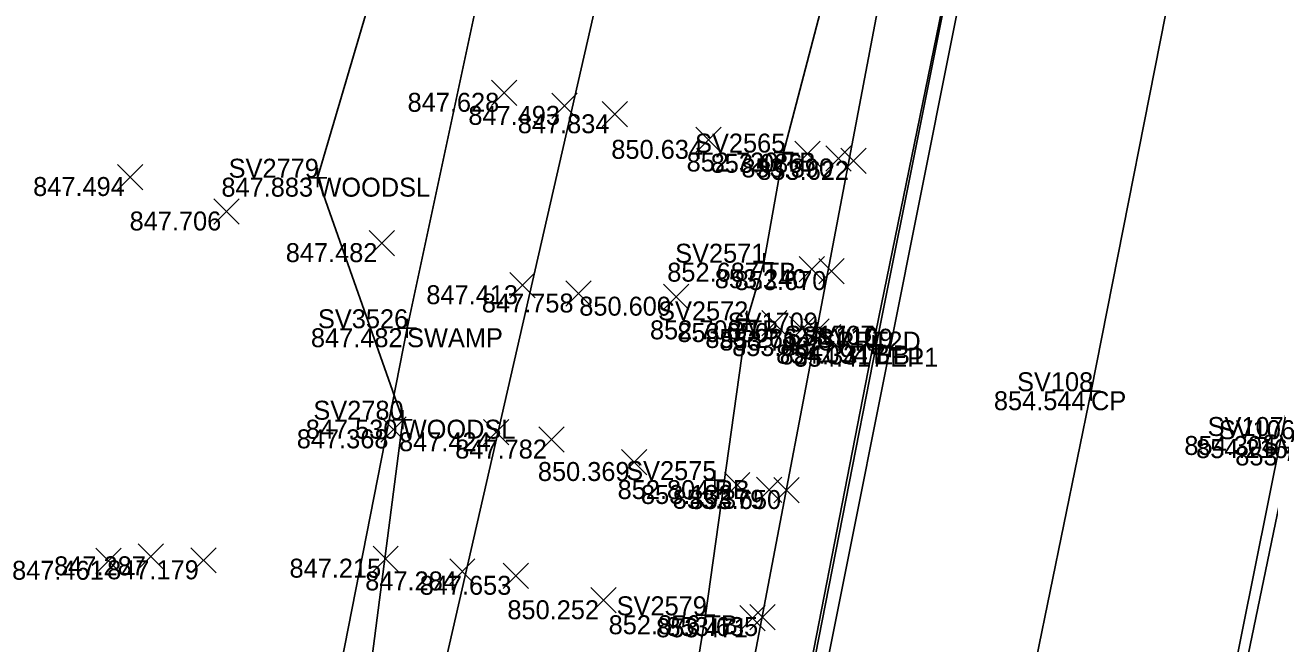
# Model space of a CAD drawing. Extents: x 2228183 to 2230895, y 679226 to 682223.
# Drawn here: x 2228275.5 to 2228341.1, y 680675.1 to 680707.7 of the extents above; entities that cross this region are included whole.
import ezdxf

# ---------------------------------------------------------------- set-up
doc = ezdxf.new("R2010")
doc.units = 0
for name, color, linetype in [('HY_X_Water_Edge', 7, 'Continuous'), ('PV_X_COP', 7, 'Continuous'), ('PV_X_EOP', 7, 'Continuous'), ('PV_X_Shoulder_Aggregate', 7, 'Continuous'), ('RD_X_GR_Rt', 7, 'Continuous'), ('SC_Scratch1', 7, 'Continuous'), ('SV_P_Control_Cells_Set', 7, 'Continuous'), ('SV_X_Break_Lines', 7, 'Continuous'), ('SV_X_Random_Point', 7, 'Continuous'), ('SV_X_Shot_Marker', 7, 'Continuous'), ('SV_X_Text_Comment', 7, 'Continuous'), ('SV_X_Top_of_Bank', 7, 'Continuous'), ('UT_X_Water', 7, 'Continuous'), ('VG_X_Tree_Line_Rt', 7, 'Continuous')]:
    doc.layers.add(name, color=color, linetype=linetype)

msp = doc.modelspace()

# ---------------------------------------------------------------- linework, layer by layer
at = {"layer": 'HY_X_Water_Edge'}
msp.add_lwpolyline([(2228257.254, 680599.372), (2228272.802, 680617.571), (2228282.168, 680631.469), (2228288.524, 680655.152), (2228295.689, 680691.668), (2228303.446, 680727.882), (2228301.785, 680777.477), (2228295.766, 680798.984)], dxfattribs=at)
at = {"layer": 'PV_X_COP'}
msp.add_lwpolyline([(2228326.722, 680663.726), (2228331.754, 680688.345), (2228336.524, 680712.498), (2228341.43, 680737.322), (2228346.158, 680761.464), (2228351.192, 680786.345), (2228355.877, 680809.999), (2228360.846, 680834.68), (2228365.727, 680859.369), (2228370.534, 680883.512), (2228375.578, 680908.155), (2228380.641, 680932.739), (2228385.533, 680957.104), (2228390.417, 680981.565)], dxfattribs=at)
at = {"layer": 'PV_X_EOP'}
for points in [[(2228316.271, 680666.166), (2228321.17, 680690.642), (2228325.981, 680714.788), (2228330.885, 680739.479), (2228335.691, 680763.827), (2228340.555, 680788.666), (2228345.277, 680812.618), (2228350.247, 680837.119), (2228355.301, 680861.724), (2228360.108, 680885.906), (2228365.09, 680910.821), (2228370.043, 680935.115), (2228374.935, 680959.317), (2228379.826, 680983.84)], [(2228336.903, 680661.667), (2228341.796, 680685.984), (2228346.631, 680710.376), (2228351.501, 680734.874), (2228356.245, 680759.284), (2228361.077, 680783.608), (2228365.966, 680808.133), (2228370.927, 680832.455), (2228375.827, 680856.961), (2228380.73, 680881.352), (2228385.664, 680905.987), (2228390.725, 680930.452), (2228395.696, 680954.82), (2228400.463, 680979.305)]]:
    msp.add_lwpolyline(points, dxfattribs=at)
at = {"layer": 'PV_X_Shoulder_Aggregate'}
for points in [[(2228315.628, 680666.277), (2228320.418, 680690.758), (2228325.257, 680714.912), (2228330.316, 680739.567), (2228335.324, 680763.916), (2228340.217, 680788.76), (2228345.101, 680812.661), (2228350.01, 680837.187), (2228354.942, 680861.825), (2228359.826, 680886.012), (2228364.882, 680910.859), (2228369.759, 680935.173), (2228374.64, 680959.326), (2228379.525, 680983.909)], [(2228337.368, 680661.526), (2228342.398, 680685.817), (2228347.341, 680710.233), (2228352.226, 680734.701), (2228356.994, 680759.156), (2228361.948, 680783.457), (2228366.728, 680807.919), (2228371.672, 680832.299), (2228376.565, 680856.801), (2228381.526, 680881.171), (2228386.516, 680905.781), (2228391.544, 680930.308), (2228396.514, 680954.638), (2228401.402, 680979.089)]]:
    msp.add_lwpolyline(points, dxfattribs=at)
at = {"layer": 'RD_X_GR_Rt'}
msp.add_lwpolyline([(2228336.966, 680805.161), (2228336.298, 680795.662), (2228335.499, 680789.809), (2228333.893, 680778.872), (2228331.445, 680764.638), (2228326.714, 680740.424), (2228321.884, 680715.76), (2228317.277, 680691.491), (2228312.595, 680666.948)], dxfattribs=at)
at = {"layer": 'SV_X_Break_Lines'}
msp.add_lwpolyline([(2228340.141, 680788.739), (2228338.031, 680778.231), (2228335.15, 680763.928), (2228332.621, 680751.514), (2228330.275, 680739.607), (2228325.198, 680714.925), (2228320.273, 680690.8), (2228315.504, 680666.348)], dxfattribs=at)
at = {"layer": 'SV_X_Random_Point'}
for p, q in [((2228300.146, 680703.419), (2228301.48, 680704.754)), ((2228300.146, 680704.754), (2228301.48, 680703.419)), ((2228303.316, 680702.73), (2228304.65, 680704.065)), ((2228303.316, 680704.065), (2228304.65, 680702.73)), ((2228305.979, 680702.287), (2228307.313, 680703.622)), ((2228305.979, 680703.622), (2228307.313, 680702.287)), ((2228310.912, 680700.937), (2228312.246, 680702.272)), ((2228310.912, 680702.272), (2228312.246, 680700.937)), ((2228316.133, 680700.201), (2228317.467, 680701.536)), ((2228316.133, 680701.536), (2228317.467, 680700.201)), ((2228317.763, 680699.957), (2228319.097, 680701.292)), ((2228317.763, 680701.292), (2228319.097, 680699.957)), ((2228318.563, 680699.828), (2228319.897, 680701.163)), ((2228318.563, 680701.163), (2228319.897, 680699.828)), ((2228280.424, 680698.977), (2228281.758, 680700.312)), ((2228280.424, 680700.312), (2228281.758, 680698.977)), ((2228285.493, 680697.158), (2228286.827, 680698.493)), ((2228285.493, 680698.493), (2228286.827, 680697.158)), ((2228293.696, 680695.489), (2228295.03, 680696.824)), ((2228293.696, 680696.824), (2228295.03, 680695.489)), ((2228316.358, 680694.111), (2228317.692, 680695.446)), ((2228316.358, 680695.446), (2228317.692, 680694.111)), ((2228317.409, 680694.016), (2228318.743, 680695.351)), ((2228317.409, 680695.351), (2228318.743, 680694.016)), ((2228301.1, 680693.27), (2228302.434, 680694.605)), ((2228301.1, 680694.605), (2228302.434, 680693.27)), ((2228304.063, 680692.832), (2228305.397, 680694.167)), ((2228304.063, 680694.167), (2228305.397, 680692.832)), ((2228309.215, 680692.665), (2228310.549, 680694)), ((2228309.215, 680694), (2228310.549, 680692.665)), ((2228314.387, 680691.273), (2228315.721, 680692.608)), ((2228314.387, 680692.608), (2228315.721, 680691.273)), ((2228315.851, 680690.961), (2228317.185, 680692.296)), ((2228315.851, 680692.296), (2228317.185, 680690.961)), ((2228316.61, 680690.824), (2228317.944, 680692.159)), ((2228316.61, 680692.159), (2228317.944, 680690.824)), ((2228317.233, 680690.533), (2228318.567, 680691.868)), ((2228317.233, 680691.868), (2228318.567, 680690.533)), ((2228294.305, 680685.667), (2228295.639, 680687.002)), ((2228294.305, 680687.002), (2228295.639, 680685.667)), ((2228299.717, 680685.515), (2228301.051, 680686.85)), ((2228299.717, 680686.85), (2228301.051, 680685.515)), ((2228302.633, 680685.128), (2228303.967, 680686.463)), ((2228302.633, 680686.463), (2228303.967, 680685.128)), ((2228307.002, 680683.944), (2228308.336, 680685.279)), ((2228307.002, 680685.279), (2228308.336, 680683.944)), ((2228312.428, 680682.731), (2228313.762, 680684.066)), ((2228312.428, 680684.066), (2228313.762, 680682.731)), ((2228314.109, 680682.481), (2228315.443, 680683.816)), ((2228314.109, 680683.816), (2228315.443, 680682.481)), ((2228315.024, 680682.465), (2228316.358, 680683.8)), ((2228315.024, 680683.8), (2228316.358, 680682.465)), ((2228279.274, 680678.732), (2228280.608, 680680.067)), ((2228279.274, 680680.067), (2228280.608, 680678.732)), ((2228281.505, 680678.968), (2228282.839, 680680.303)), ((2228281.505, 680680.303), (2228282.839, 680678.968)), ((2228284.287, 680678.758), (2228285.621, 680680.093)), ((2228284.287, 680680.093), (2228285.621, 680678.758)), ((2228293.891, 680678.845), (2228295.225, 680680.18)), ((2228293.891, 680680.18), (2228295.225, 680678.845)), ((2228297.934, 680678.173), (2228299.268, 680679.508)), ((2228297.934, 680679.508), (2228299.268, 680678.173)), ((2228300.748, 680677.942), (2228302.082, 680679.277)), ((2228300.748, 680679.277), (2228302.082, 680677.942)), ((2228305.382, 680676.651), (2228306.716, 680677.986)), ((2228305.382, 680677.986), (2228306.716, 680676.651)), ((2228313.234, 680675.699), (2228314.568, 680677.034)), ((2228313.234, 680677.034), (2228314.568, 680675.699)), ((2228313.769, 680675.765), (2228315.103, 680677.1)), ((2228313.769, 680677.1), (2228315.103, 680675.765))]:
    msp.add_line(p, q, dxfattribs=at)
at = {"layer": 'SV_X_Shot_Marker'}
for p, q in [((2228315.043, 680700.935), (2228316.043, 680700.935)), ((2228315.543, 680701.435), (2228315.543, 680700.435)), ((2228315.543, 680700.935), (2228315.543, 680700.935)), ((2228290.46, 680699.609), (2228291.46, 680699.609)), ((2228290.96, 680700.109), (2228290.96, 680699.109)), ((2228290.96, 680699.609), (2228290.96, 680699.609)), ((2228314.004, 680695.125), (2228315.004, 680695.125)), ((2228314.504, 680695.625), (2228314.504, 680694.625)), ((2228314.504, 680695.125), (2228314.504, 680695.125)), ((2228313.596, 680692.583), (2228313.596, 680691.583)), ((2228295.689, 680692.168), (2228295.689, 680691.168)), ((2228313.096, 680692.083), (2228314.096, 680692.083)), ((2228313.596, 680692.083), (2228313.596, 680692.083)), ((2228317.277, 680691.991), (2228317.277, 680690.991)), ((2228295.189, 680691.668), (2228296.189, 680691.668)), ((2228295.689, 680691.668), (2228295.689, 680691.668)), ((2228316.777, 680691.491), (2228317.777, 680691.491)), ((2228317.277, 680691.491), (2228317.277, 680691.491)), ((2228320.273, 680691.3), (2228320.273, 680690.3)), ((2228320.418, 680691.258), (2228320.418, 680690.258)), ((2228321.17, 680691.142), (2228321.17, 680690.142)), ((2228319.773, 680690.8), (2228320.773, 680690.8)), ((2228319.918, 680690.758), (2228320.918, 680690.758)), ((2228320.273, 680690.8), (2228320.273, 680690.8)), ((2228320.418, 680690.758), (2228320.418, 680690.758)), ((2228320.67, 680690.642), (2228321.67, 680690.642)), ((2228321.17, 680690.642), (2228321.17, 680690.642)), ((2228331.754, 680688.845), (2228331.754, 680687.845)), ((2228331.254, 680688.345), (2228332.254, 680688.345)), ((2228331.754, 680688.345), (2228331.754, 680688.345)), ((2228295.459, 680687.343), (2228295.459, 680686.343)), ((2228294.959, 680686.843), (2228295.959, 680686.843)), ((2228295.459, 680686.843), (2228295.459, 680686.843)), ((2228311.911, 680684.157), (2228311.911, 680683.157)), ((2228311.411, 680683.657), (2228312.411, 680683.657)), ((2228311.911, 680683.657), (2228311.911, 680683.657)), ((2228311.42, 680677.026), (2228311.42, 680676.026)), ((2228310.92, 680676.526), (2228311.92, 680676.526)), ((2228311.42, 680676.526), (2228311.42, 680676.526))]:
    msp.add_line(p, q, dxfattribs=at)
at = {"layer": 'SV_X_Top_of_Bank'}
msp.add_lwpolyline([(2228333.828, 680790.023), (2228330.949, 680779.592), (2228328.52, 680765.099), (2228325.98, 680752.782), (2228323.422, 680741.195), (2228322.806, 680738.094), (2228321.225, 680733.302), (2228320.821, 680729.418), (2228320.197, 680724.653), (2228318.479, 680716.492), (2228317.954, 680710.16), (2228315.543, 680700.935), (2228314.504, 680695.125), (2228313.596, 680692.083), (2228311.42, 680676.526), (2228310.436, 680670.495)], dxfattribs=at)
at = {"layer": 'UT_X_Water'}
msp.add_lwpolyline([(2228281.807, 680604.546), (2228316.003, 680754.006)], dxfattribs=at)
at = {"layer": 'VG_X_Tree_Line_Rt'}
msp.add_lwpolyline([(2228242.224, 680398.608), (2228254.757, 680454.617), (2228285.377, 680608.953), (2228295.459, 680686.843), (2228290.96, 680699.609), (2228297.38, 680721.363), (2228313.146, 680792.869)], dxfattribs=at)

# ---------------------------------------------------------------- texts
at = {"layer": 'SC_Scratch1'}
for s, p in [('847.628', (2228295.713, 680703.086)), ('847.493', (2228298.919, 680702.397)), ('847.834', (2228301.524, 680701.954)), ('850.634', (2228306.457, 680700.604)), ('852.720', (2228310.429, 680699.935)), ('853.086', (2228311.696, 680699.868)), ('853.390', (2228313.316, 680699.624)), ('853.622', (2228314.157, 680699.495)), ('847.494', (2228275.969, 680698.644)), ('847.883', (2228285.896, 680698.609)), ('847.706', (2228281.056, 680696.825)), ('847.482', (2228289.29, 680695.156)), ('852.687', (2228309.408, 680694.125)), ('853.240', (2228311.911, 680693.778)), ('853.670', (2228312.962, 680693.683)), ('847.413', (2228296.703, 680692.937)), ('847.758', (2228299.63, 680692.499)), ('850.600', (2228304.768, 680692.332)), ('852.708', (2228308.496, 680691.083)), ('853.050', (2228309.94, 680690.94)), ('847.482', (2228290.616, 680690.668)), ('853.266', (2228311.414, 680690.628)), ('853.714', (2228312.155, 680690.491)), ('853.714', (2228312.155, 680690.491)), ('853.862', (2228312.827, 680690.2)), ('854.094', (2228315.151, 680689.8)), ('854.331', (2228315.336, 680689.758)), ('854.417', (2228316.074, 680689.642)), ('854.544', (2228326.632, 680687.345)), ('847.530', (2228290.345, 680685.843)), ('847.368', (2228289.872, 680685.334)), ('847.424', (2228295.262, 680685.182)), ('854.304', (2228336.674, 680684.984)), ('854.216', (2228337.294, 680684.817)), ('847.782', (2228298.227, 680684.795)), ('853.774', (2228339.361, 680684.429)), ('850.369', (2228302.585, 680683.611)), ('852.804', (2228306.789, 680682.657)), ('853.132', (2228308.022, 680682.398)), ('853.379', (2228309.692, 680682.148)), ('853.650', (2228310.577, 680682.132)), ('847.461', (2228274.859, 680678.399)), ('847.287', (2228277.076, 680678.635)), ('847.179', (2228279.87, 680678.425)), ('847.215', (2228289.488, 680678.512)), ('847.284', (2228293.479, 680677.84)), ('847.653', (2228296.351, 680677.609)), ('850.252', (2228300.976, 680676.318)), ('852.876', (2228306.316, 680675.526)), ('853.471', (2228308.819, 680675.366)), ('853.635', (2228309.366, 680675.432))]:
    msp.add_text(s, height=1, dxfattribs=at).set_placement(p)
at = {"layer": 'SV_P_Control_Cells_Set'}
for s, p in [('SV2565', (2228310.874, 680700.935)), ('SV2779', (2228286.278, 680699.609)), ('SV2571', (2228309.824, 680695.125)), ('SV2572', (2228308.925, 680692.083)), ('SV3526', (2228290.987, 680691.668)), ('SV1709', (2228312.595, 680691.491)), ('SV1707', (2228315.579, 680690.8)), ('SV110', (2228316.504, 680690.758)), ('SV109', (2228317.286, 680690.642)), ('SV108', (2228327.854, 680688.345)), ('SV2780', (2228290.747, 680686.843)), ('SV107', (2228337.9, 680685.984)), ('SV106', (2228338.494, 680685.817)), ('SV240_1', (2228340.779, 680685.06)), ('SV2575', (2228307.242, 680683.657)), ('SV2579', (2228306.738, 680676.526))]:
    msp.add_text(s, height=1, dxfattribs=at).set_placement(p)
at = {"layer": 'SV_X_Text_Comment'}
for s, p in [('TB', (2228315.543, 680699.935)), ('WOODSL', (2228290.96, 680698.609)), ('TB', (2228314.504, 680694.125)), ('TB', (2228313.596, 680691.083)), ('SWAMP', (2228295.689, 680690.668)), ('GRRT2D', (2228317.277, 680690.491)), ('B', (2228320.273, 680689.8)), ('EB1', (2228320.418, 680689.758)), ('EP1', (2228321.17, 680689.642)), ('CP', (2228331.754, 680687.345)), ('WOODSL', (2228295.459, 680685.843)), ('RB', (2228311.911, 680682.657)), ('TB', (2228311.42, 680675.526))]:
    msp.add_text(s, height=1, dxfattribs=at).set_placement(p)

doc.saveas('drawing.dxf')
